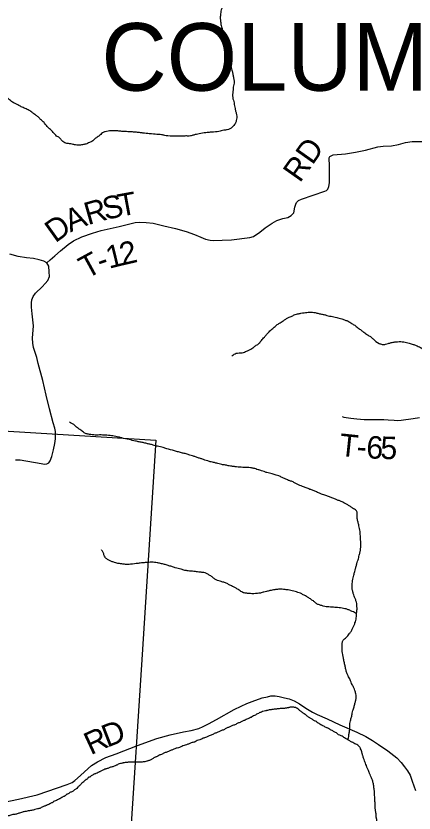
# Model space of a CAD drawing. Extents: x -13.7 to 34, y 0 to 32.3.
# Drawn here: x 27.443 to 28.447, y 15.995 to 18.005 of the extents above; entities that cross this region are included whole.
import ezdxf

# ---------------------------------------------------------------- set-up
doc = ezdxf.new("R2010")
doc.units = 0
for name, color, linetype in [('GM_X_Corporation', 7, 'Continuous'), ('GM_X_County_Road', 7, 'Continuous'), ('GM_X_County_Road_Text', 7, 'Continuous'), ('GM_X_Minor_River', 7, 'Continuous'), ('GM_X_Township_Road', 7, 'Continuous'), ('GM_X_Township_Road_Text', 7, 'Continuous'), ('GM_X_Township_Text', 7, 'Continuous')]:
    doc.layers.add(name, color=color, linetype=linetype)

msp = doc.modelspace()

# ---------------------------------------------------------------- linework, layer by layer
at = {"layer": 'GM_X_Corporation'}
msp.add_lwpolyline([(27.2726, 16.9674), (27.7957, 16.9352), (27.7886, 16.8172), (27.7611, 16.3953), (27.73, 15.9158), (26.7165, 15.9781), (26.789, 16.9963)], close=True, dxfattribs=at)
at = {"layer": 'GM_X_County_Road'}
msp.add_lwpolyline([(27.4097, 16.0217), (27.4494, 16.0299), (27.4968, 16.0413), (27.5727, 16.0673), (27.5846, 16.0726), (27.5918, 16.0776), (27.6056, 16.0899), (27.6252, 16.1077), (27.6338, 16.1151), (27.6488, 16.1247), (27.6695, 16.1352), (27.6957, 16.145), (27.7496, 16.1658), (27.7986, 16.183), (27.8324, 16.1921), (27.8654, 16.1998), (27.8845, 16.2033), (27.9043, 16.2082), (27.9153, 16.2132), (27.9286, 16.2204), (27.9491, 16.2314), (27.9931, 16.2563), (28.0108, 16.265), (28.0253, 16.2715), (28.0386, 16.2764), (28.0642, 16.2855), (28.0769, 16.2886), (28.0855, 16.2906), (28.0967, 16.2907), (28.107, 16.2888), (28.1205, 16.2858), (28.1321, 16.2832), (28.1441, 16.2785), (28.1579, 16.2704), (28.1737, 16.2601), (28.1903, 16.2498), (28.2024, 16.2442), (28.2278, 16.2326), (28.2594, 16.2181), (28.3023, 16.1992), (28.3248, 16.1884), (28.3418, 16.1782), (28.3567, 16.1684), (28.3803, 16.152), (28.4029, 16.1349), (28.4141, 16.1226), (28.423, 16.1121), (28.4303, 16.102), (28.4368, 16.0906), (28.4421, 16.0757), (28.4505, 16.0525)], dxfattribs=at)
at = {"layer": 'GM_X_Minor_River'}
for points in [[(27.9701, 18.0943), (27.9736, 18.0854), (27.9749, 18.0789), (27.9773, 18.0708), (27.9774, 18.0636), (27.9776, 18.0571), (27.9758, 18.0485), (27.9721, 18.0418), (27.9677, 18.0347), (27.9644, 18.0276), (27.9604, 18.0212), (27.9594, 18.0141), (27.9588, 18.0076), (27.9582, 17.9989), (27.9591, 17.9913), (27.9606, 17.9813), (27.9627, 17.9741), (27.9635, 17.966), (27.964, 17.958), (27.9649, 17.9512), (27.9666, 17.9443), (27.969, 17.9374), (27.9714, 17.9289), (27.9726, 17.9186), (27.9739, 17.911), (27.9744, 17.9037), (27.9772, 17.8964), (27.9822, 17.8887), (27.9843, 17.8821), (27.9876, 17.8684), (27.9897, 17.8603), (27.9912, 17.8508), (27.9932, 17.8423), (27.993, 17.8359), (27.9913, 17.8295), (27.9907, 17.8227), (27.9901, 17.8151), (27.9896, 17.7999), (27.9912, 17.7934), (27.9929, 17.7861), (27.9945, 17.7785), (27.9958, 17.7719), (27.9975, 17.7635), (27.9995, 17.7559), (28, 17.7486), (27.9986, 17.7415), (27.9957, 17.7336), (27.9894, 17.7258), (27.9824, 17.7203), (27.9758, 17.7183), (27.9674, 17.717), (27.9544, 17.7137), (27.9373, 17.7123), (27.9285, 17.7115), (27.9221, 17.7109), (27.9049, 17.7081), (27.8984, 17.7068), (27.8915, 17.7051), (27.8831, 17.7027), (27.8759, 17.7026), (27.8664, 17.7025), (27.8588, 17.702), (27.8504, 17.7019), (27.8261, 17.7027), (27.8182, 17.7041), (27.8103, 17.7059), (27.8027, 17.7065), (27.7853, 17.7079), (27.7789, 17.7085), (27.7717, 17.7091), (27.7634, 17.7101), (27.7547, 17.7112), (27.7445, 17.7123), (27.7346, 17.713), (27.7282, 17.7132), (27.7217, 17.7138), (27.7123, 17.7141), (27.7028, 17.7152), (27.6922, 17.7159), (27.6823, 17.7155), (27.6755, 17.7149), (27.6682, 17.7133), (27.6616, 17.7105), (27.6523, 17.7024), (27.6441, 17.697), (27.6367, 17.6904), (27.6286, 17.6861), (27.6193, 17.6822), (27.6113, 17.6806), (27.6006, 17.6794), (27.5931, 17.68), (27.5852, 17.6818), (27.578, 17.6832), (27.5693, 17.6843), (27.5593, 17.6911), (27.5527, 17.6981), (27.5456, 17.7025)], [(27.5456, 17.7025), (27.5375, 17.7115), (27.5276, 17.721), (27.5199, 17.7288), (27.5141, 17.7366), (27.5056, 17.7441), (27.499, 17.7508), (27.4923, 17.756), (27.4853, 17.7611), (27.4768, 17.7671), (27.4667, 17.772), (27.4566, 17.7765), (27.4484, 17.781), (27.4416, 17.7842), (27.432, 17.7899), (27.4227, 17.7978), (27.415, 17.8041), (27.4083, 17.8097), (27.4017, 17.8148), (27.3954, 17.82), (27.3891, 17.8247), (27.3817, 17.8299), (27.3724, 17.8356), (27.3656, 17.8388), (27.3585, 17.8425), (27.3495, 17.8458), (27.3417, 17.8499), (27.3353, 17.8524), (27.3278, 17.8549), (27.3203, 17.8563), (27.3127, 17.8558), (27.3054, 17.8545), (27.2989, 17.8536), (27.2898, 17.852), (27.2817, 17.8496), (27.2748, 17.8483), (27.2672, 17.8466), (27.2572, 17.8439), (27.2507, 17.8426), (27.2431, 17.8406), (27.2366, 17.8393), (27.227, 17.8373), (27.2182, 17.8357), (27.2102, 17.8341), (27.2029, 17.8317), (27.1945, 17.8285), (27.1863, 17.8242), (27.1798, 17.8199)], [(27.9877, 17.1483), (27.9955, 17.1534), (28.002, 17.1554), (28.01, 17.1555), (28.0172, 17.1568), (28.0265, 17.1611), (28.0334, 17.1639), (28.042, 17.1697), (28.049, 17.1748), (28.0563, 17.1798), (28.0619, 17.1869), (28.0694, 17.1954), (28.0749, 17.202), (28.0812, 17.209), (28.091, 17.2175), (28.098, 17.2237), (28.1062, 17.2299), (28.117, 17.2363), (28.1237, 17.2411), (28.1302, 17.245), (28.1387, 17.2482), (28.1468, 17.2525), (28.1533, 17.2541), (28.1617, 17.2558), (28.1694, 17.257), (28.1762, 17.2579), (28.1835, 17.2585), (28.1907, 17.2582), (28.1975, 17.2572), (28.2065, 17.255), (28.2152, 17.2532), (28.2235, 17.2514), (28.2302, 17.2493), (28.2374, 17.2479), (28.2446, 17.2469), (28.2517, 17.2448), (28.2581, 17.2431), (28.2649, 17.2413), (28.2731, 17.2384), (28.2806, 17.2355), (28.2892, 17.2299), (28.297, 17.2254), (28.3051, 17.2191), (28.3137, 17.2127), (28.3203, 17.2076), (28.3292, 17.2012), (28.3367, 17.1968), (28.3437, 17.1908), (28.3585, 17.1797), (28.3664, 17.1772), (28.3748, 17.1776), (28.3813, 17.1793), (28.3893, 17.1817), (28.3985, 17.1833), (28.405, 17.1839), (28.4133, 17.184), (28.4205, 17.1837), (28.428, 17.182), (28.4344, 17.1802), (28.4442, 17.1772), (28.4521, 17.1743), (28.4626, 17.1694), (28.4723, 17.1649), (28.4798, 17.1631), (28.4897, 17.1624), (28.4961, 17.1622), (28.5026, 17.1624), (28.509, 17.1622), (28.5177, 17.1615), (28.5264, 17.1601), (28.5328, 17.1587), (28.5404, 17.1577), (28.5468, 17.1571), (28.5559, 17.1564), (28.5631, 17.1551), (28.5709, 17.1521), (28.578, 17.1493), (28.5863, 17.1459), (28.5942, 17.1438), (28.6021, 17.1424), (28.6086, 17.1425), (28.6174, 17.1468), (28.6244, 17.15), (28.6318, 17.157), (28.6408, 17.165), (28.6475, 17.172), (28.6542, 17.1798), (28.6645, 17.1908), (28.6719, 17.1967), (28.6789, 17.2018), (28.6859, 17.2084), (28.6929, 17.2116), (28.7006, 17.2155), (28.7079, 17.2187), (28.7175, 17.2229), (28.7252, 17.2261), (28.7326, 17.2304)], [(28.1217, 16.8384), (28.1142, 16.8416), (28.1056, 16.8453), (28.0989, 16.8471), (28.0887, 16.8505), (28.0759, 16.8539), (28.0688, 16.8564), (28.0624, 16.8586), (28.0534, 16.8611), (28.0429, 16.8645), (28.0346, 16.8659), (28.0266, 16.867), (28.0194, 16.8668), (28.0107, 16.8671), (28.0031, 16.8677), (27.9959, 16.8687), (27.9872, 16.8698), (27.9804, 16.8708), (27.9714, 16.8726), (27.9619, 16.8741), (27.9492, 16.8775), (27.9416, 16.8793), (27.9352, 16.8806), (27.9266, 16.8832), (27.9194, 16.8853), (27.9119, 16.8883), (27.9044, 16.8904), (27.8962, 16.8933), (27.8886, 16.8959), (27.8815, 16.898), (27.8725, 16.901), (27.8627, 16.9032), (27.8529, 16.9058), (27.8428, 16.9088), (27.8232, 16.914), (27.8142, 16.9169), (27.8002, 16.9201), (27.7893, 16.9231), (27.781, 16.9253), (27.7728, 16.9271), (27.7637, 16.9293), (27.7539, 16.9311), (27.7449, 16.9333), (27.7283, 16.9369), (27.7102, 16.9413), (27.7019, 16.9435), (27.6876, 16.9462), (27.6808, 16.9472), (27.6725, 16.9482), (27.6645, 16.9485), (27.6581, 16.9487), (27.6505, 16.9486), (27.6433, 16.9485), (27.6353, 16.9491), (27.6285, 16.9501), (27.6206, 16.9519), (27.6135, 16.9555), (27.6046, 16.9623), (27.5983, 16.9667), (27.5906, 16.9738), (27.5843, 16.9778), (27.5779, 16.9806)], [(28.2792, 16.1805), (28.2816, 16.1852), (28.2825, 16.1916), (28.2836, 16.1999), (28.2846, 16.2071), (28.2844, 16.2136), (28.285, 16.2208), (28.2864, 16.228), (28.289, 16.2374), (28.2908, 16.2468), (28.2926, 16.2536), (28.2955, 16.263), (28.2977, 16.2717), (28.2999, 16.2796), (28.3005, 16.2883), (28.3, 16.2963), (28.2973, 16.3044), (28.2952, 16.3109), (28.2906, 16.3194), (28.2856, 16.3314), (28.2806, 16.341), (28.2775, 16.3487), (28.2747, 16.3576), (28.2728, 16.3667), (28.2704, 16.3763), (28.2685, 16.3863), (28.2669, 16.3951), (28.2656, 16.4023), (28.2651, 16.4099), (28.2653, 16.4175), (28.2656, 16.4244), (28.2684, 16.4315), (28.2755, 16.4377), (28.283, 16.447), (28.2878, 16.4533), (28.2914, 16.4604), (28.2951, 16.4671), (28.2976, 16.4746), (28.2997, 16.481), (28.301, 16.4874), (28.3017, 16.495), (28.3023, 16.5022), (28.303, 16.5116), (28.3025, 16.52), (28.3016, 16.5269), (28.2988, 16.5346), (28.296, 16.5419), (28.2936, 16.5488), (28.2916, 16.5569), (28.2907, 16.5652), (28.291, 16.5744), (28.2916, 16.5812), (28.293, 16.5884), (28.2948, 16.5955), (28.2973, 16.6042), (28.2991, 16.6117), (28.3012, 16.6196), (28.3034, 16.6271), (28.3055, 16.6335), (28.3086, 16.6456), (28.3107, 16.6543), (28.3121, 16.6618), (28.3128, 16.6694), (28.3126, 16.6759), (28.3121, 16.6839), (28.3116, 16.6911), (28.3111, 16.6979), (28.3105, 16.7052), (28.3089, 16.7125), (28.3076, 16.7197), (28.3056, 16.7289), (28.3036, 16.7377), (28.3031, 16.7446), (28.3037, 16.751), (28.3013, 16.7575), (28.2916, 16.7643), (28.2849, 16.7691), (28.2782, 16.7731), (28.2715, 16.7768), (28.2633, 16.7808), (28.2558, 16.7838), (28.2487, 16.7867), (28.2397, 16.79), (28.2311, 16.7933), (28.2221, 16.7967), (28.2104, 16.8008), (28.2007, 16.805), (28.1928, 16.8083), (28.1842, 16.8116), (28.1749, 16.8153), (28.1659, 16.819), (28.1591, 16.8215), (28.1524, 16.8244), (28.1457, 16.8281), (28.1374, 16.8318), (28.1299, 16.8343), (28.1217, 16.8384)], [(28.302, 16.4983), (28.291, 16.5037), (28.2827, 16.5074), (28.2752, 16.5099), (28.2688, 16.5113), (28.2616, 16.5126), (28.2541, 16.5133), (28.2473, 16.5139), (28.2393, 16.5145), (28.2321, 16.5151), (28.2253, 16.5157), (28.2178, 16.5171), (28.2099, 16.5197), (28.2027, 16.5222), (28.1961, 16.5277), (28.1894, 16.5325), (28.1816, 16.5377), (28.1753, 16.5417), (28.1675, 16.5458), (28.1604, 16.5494), (28.1536, 16.5516), (28.1469, 16.5541), (28.1397, 16.5554), (28.1329, 16.5572), (28.1265, 16.5582), (28.1178, 16.5592), (28.1049, 16.5596), (28.0954, 16.5584), (28.0835, 16.5562), (28.0751, 16.5542), (28.0682, 16.5525), (28.0594, 16.5501), (28.0518, 16.5489), (28.043, 16.5484), (28.032, 16.5487), (28.0226, 16.5498), (28.015, 16.5516), (28.0058, 16.5576), (27.9983, 16.562), (27.9912, 16.5657), (27.9826, 16.5701), (27.9755, 16.5738), (27.9669, 16.5771), (27.9579, 16.5797), (27.9511, 16.5815), (27.9444, 16.5851), (27.9381, 16.5906), (27.9303, 16.5954), (27.9232, 16.5995), (27.9165, 16.6016), (27.9078, 16.6026), (27.9006, 16.6036), (27.8915, 16.6047), (27.8772, 16.6059), (27.8692, 16.6073), (27.8594, 16.6099), (27.8523, 16.6121), (27.8448, 16.6135), (27.8358, 16.6168), (27.8267, 16.6194), (27.8173, 16.6224), (27.8075, 16.6246), (27.7989, 16.6264), (27.7921, 16.6274), (27.7856, 16.6276), (27.7773, 16.6275), (27.7708, 16.6269), (27.762, 16.6261), (27.7514, 16.6249), (27.7323, 16.6225), (27.7243, 16.6224), (27.7145, 16.6227), (27.7065, 16.6241), (27.6979, 16.6252), (27.6915, 16.6273), (27.6843, 16.6298), (27.6776, 16.6327), (27.6709, 16.6375), (27.6659, 16.6449), (27.6631, 16.6522), (27.6587, 16.6588)], [(28.1641, 16.2495), (28.1619, 16.2515), (28.1593, 16.2531), (28.1567, 16.2554), (28.1545, 16.2578), (28.1519, 16.2594), (28.1497, 16.2606), (28.1474, 16.2615), (28.144, 16.2619), (28.1364, 16.2622), (28.1326, 16.2616), (28.1299, 16.2609), (28.1269, 16.2602), (28.1238, 16.26), (28.12, 16.2593), (28.1139, 16.2588), (28.1113, 16.2585), (28.109, 16.2586), (28.1044, 16.2579), (28.1014, 16.2577), (28.0987, 16.2574), (28.0941, 16.2571), (28.0895, 16.2562), (28.0865, 16.2559), (28.0842, 16.2556), (28.0796, 16.255), (28.075, 16.2536), (28.0724, 16.2533), (28.0658, 16.2512), (28.0628, 16.2506), (28.0605, 16.2491), (28.0582, 16.2485), (28.0551, 16.2467), (28.0497, 16.2446), (28.0473, 16.2424), (28.0416, 16.2403), (28.0373, 16.2374), (28.0346, 16.2359), (28.0296, 16.2334), (28.0254, 16.2324), (28.0211, 16.2295), (28.0173, 16.2285), (28.0142, 16.2271), (28.008, 16.2239), (28.0042, 16.2225), (28.0007, 16.2211), (27.9934, 16.2172), (27.9891, 16.2162), (27.9861, 16.2147), (27.9791, 16.2112), (27.9757, 16.2102), (27.9726, 16.2087), (27.9652, 16.2044), (27.961, 16.2034), (27.9579, 16.202), (27.9506, 16.1981), (27.9468, 16.1971), (27.9433, 16.1956), (27.9352, 16.1914), (27.9306, 16.19), (27.9232, 16.1864), (27.9186, 16.1851), (27.9148, 16.1837), (27.9067, 16.1801), (27.9002, 16.1785), (27.8952, 16.1752), (27.8871, 16.1728), (27.8798, 16.1696), (27.8763, 16.1686), (27.8733, 16.1676), (27.8671, 16.1659), (27.8614, 16.1634), (27.8556, 16.1606), (27.8495, 16.1592), (27.8456, 16.1582), (27.8375, 16.1547), (27.8341, 16.1537), (27.831, 16.1523), (27.8237, 16.1487), (27.8198, 16.1477), (27.8164, 16.1463), (27.8098, 16.1427), (27.806, 16.1417), (27.8033, 16.1403), (27.7975, 16.137), (27.7948, 16.1364), (27.7874, 16.1317), (27.7847, 16.1306), (27.7782, 16.1274), (27.7755, 16.1267), (27.7732, 16.1261), (27.7682, 16.1247), (27.7636, 16.1241), (27.7598, 16.1238), (27.7564, 16.1239), (27.7526, 16.1237), (27.7473, 16.1239)], [(28.3923, 15.9068), (28.3901, 15.9092), (28.3887, 15.9122), (28.3885, 15.9179), (28.3886, 15.9202), (28.3891, 15.924), (28.3888, 15.9271), (28.3885, 15.9305), (28.3882, 15.9328), (28.3869, 15.9374), (28.3836, 15.942), (28.3806, 15.9444), (28.3776, 15.9457), (28.3735, 15.9481), (28.3706, 15.9493), (28.3687, 15.952), (28.3658, 15.9548), (28.3626, 15.9598), (28.3593, 15.9637), (28.3567, 15.968), (28.3539, 15.973), (28.3532, 15.9757), (28.3523, 15.9815), (28.3516, 15.9841), (28.3513, 15.9868), (28.3508, 15.994), (28.3505, 15.9967), (28.3498, 15.9998), (28.349, 16.0078), (28.3483, 16.012), (28.3486, 16.0188), (28.3483, 16.0215), (28.3481, 16.028), (28.3478, 16.0302), (28.3475, 16.0329), (28.3474, 16.0398), (28.3471, 16.0443), (28.3466, 16.0516), (28.3463, 16.0539), (28.3457, 16.0588), (28.3454, 16.0622), (28.3448, 16.0661), (28.3435, 16.0714), (28.3425, 16.0753), (28.3404, 16.0814), (28.3383, 16.086), (28.3358, 16.0926), (28.3344, 16.0949), (28.3337, 16.0972), (28.332, 16.1022), (28.3284, 16.1095), (28.3277, 16.1122), (28.3267, 16.1149), (28.3242, 16.1207), (28.3224, 16.1246), (28.3207, 16.1299), (28.319, 16.1338), (28.318, 16.1384), (28.3169, 16.1411), (28.3159, 16.1453), (28.3152, 16.1476), (28.3142, 16.1518), (28.3121, 16.1572), (28.3107, 16.1599), (28.3089, 16.1622), (28.3067, 16.165), (28.3022, 16.1678), (28.2974, 16.1699), (28.2925, 16.1731), (28.2895, 16.1743), (28.2866, 16.1759), (28.2795, 16.1803), (28.2754, 16.1824), (28.268, 16.1875), (28.2631, 16.1904), (28.2564, 16.1925), (28.2512, 16.1972), (28.2467, 16.1993), (28.24, 16.2033), (28.2363, 16.2049), (28.2337, 16.2065), (28.2281, 16.2098), (28.2251, 16.211), (28.2169, 16.2155), (28.2143, 16.2167), (28.212, 16.2179), (28.2072, 16.2211), (28.205, 16.2223), (28.1987, 16.2267), (28.196, 16.2275), (28.1901, 16.2319), (28.1864, 16.2339), (28.1838, 16.2352), (28.1804, 16.2372), (28.1774, 16.2396), (28.17, 16.2455), (28.1641, 16.2495)], [(27.7473, 16.1239), (27.7443, 16.1236), (27.7344, 16.1239), (27.7298, 16.1237), (27.7264, 16.1234), (27.7218, 16.1228), (27.7184, 16.1226), (27.7138, 16.1216), (27.7112, 16.1209), (27.7066, 16.1199), (27.7012, 16.1182), (27.6973, 16.116), (27.695, 16.1153), (27.6873, 16.1122), (27.6835, 16.1112), (27.68, 16.1101), (27.6731, 16.1073), (27.6701, 16.1067), (27.6674, 16.1056), (27.6627, 16.1035), (27.6593, 16.1021), (27.6558, 16.0999), (27.6531, 16.0993), (27.6508, 16.0978), (27.645, 16.0946), (27.6419, 16.0939), (27.6396, 16.0929), (27.6361, 16.0907), (27.6327, 16.0889), (27.6291, 16.086), (27.6257, 16.0846), (27.6225, 16.0809), (27.6198, 16.0795), (27.614, 16.0743), (27.6093, 16.0707), (27.6069, 16.0674), (27.6006, 16.0615), (27.5967, 16.0574), (27.594, 16.0556), (27.5909, 16.0534), (27.5842, 16.0487), (27.5808, 16.0477), (27.5746, 16.0437), (27.5719, 16.0427), (27.5696, 16.0412), (27.5645, 16.0372), (27.5614, 16.0362), (27.5591, 16.0347), (27.5537, 16.0315), (27.551, 16.0304), (27.5483, 16.029), (27.5429, 16.0258), (27.5383, 16.0244), (27.5355, 16.0218), (27.5328, 16.0208), (27.5305, 16.0197), (27.5263, 16.0172), (27.5236, 16.0162), (27.5213, 16.0151), (27.5189, 16.014), (27.5163, 16.013), (27.5128, 16.0116), (27.5093, 16.0105), (27.5051, 16.0077), (27.5012, 16.0066), (27.4978, 16.0056), (27.4913, 16.0043), (27.4867, 16.0026), (27.4829, 16.0019), (27.4802, 16.0013), (27.4745, 16.0007), (27.4687, 15.9994), (27.463, 15.9984), (27.4596, 15.9978), (27.4549, 15.9956), (27.4504, 15.9946), (27.4431, 15.9922), (27.4385, 15.9916), (27.4328, 15.9907), (27.4236, 15.9879), (27.4186, 15.9873), (27.4151, 15.9856), (27.4125, 15.9849), (27.4094, 15.9842), (27.4071, 15.9832), (27.404, 15.9814), (27.4001, 15.9792), (27.3959, 15.9782), (27.3924, 15.9757), (27.3893, 15.9746), (27.3867, 15.974), (27.3813, 15.9719), (27.3767, 15.9712), (27.3732, 15.9695), (27.3698, 15.9688), (27.3671, 15.9681), (27.3602, 15.9665)]]:
    msp.add_spline(points, degree=3, dxfattribs=at)
at = {"layer": 'GM_X_Township_Road'}
for points in [[(27.521, 17.3827), (27.5299, 17.3903), (27.541, 17.4004), (27.5553, 17.4131), (27.575, 17.4293), (27.5882, 17.4381), (27.6093, 17.448), (27.6364, 17.4578), (27.6578, 17.4646), (27.7034, 17.4745), (27.7233, 17.4792), (27.7439, 17.4845), (27.7539, 17.4856), (27.7719, 17.4849), (27.789, 17.4825), (27.8164, 17.4757), (27.8456, 17.4694), (27.8723, 17.4617), (27.8931, 17.4543), (27.909, 17.4474), (27.9211, 17.4425), (27.9325, 17.44), (27.9415, 17.4392), (27.9627, 17.4396), (27.9862, 17.4406), (28.0326, 17.4463), (28.042, 17.4494), (28.0581, 17.4602), (28.0718, 17.4708), (28.0891, 17.4827), (28.1008, 17.4892), (28.1157, 17.4943), (28.1287, 17.4972), (28.1373, 17.5019), (28.1434, 17.509), (28.1463, 17.5231), (28.1483, 17.5307), (28.1508, 17.5348), (28.1557, 17.5398), (28.163, 17.5437), (28.2216, 17.5633), (28.2257, 17.5654), (28.2294, 17.5682), (28.2318, 17.5752), (28.2335, 17.5848), (28.2335, 17.6266), (28.2328, 17.6472), (28.2341, 17.6507), (28.2377, 17.6526), (28.2431, 17.6554), (28.2741, 17.6579), (28.2994, 17.6619), (28.3243, 17.6666), (28.3551, 17.675), (28.3686, 17.6771), (28.3896, 17.6777), (28.4072, 17.6815), (28.425, 17.6864), (28.4415, 17.6885), (28.4664, 17.6887)], [(27.4422, 16.8856), (27.4477, 16.8862), (27.4539, 16.8858), (27.5067, 16.8764), (27.5153, 16.8749), (27.5208, 16.8757), (27.5262, 16.8788), (27.5299, 16.8838), (27.5338, 16.894), (27.5377, 16.9109), (27.5415, 16.9276), (27.543, 16.9392), (27.5434, 16.9493), (27.5432, 16.9573), (27.5412, 16.9655), (27.5375, 16.979), (27.528, 17.0147), (27.5192, 17.049), (27.5108, 17.086), (27.4995, 17.1287), (27.496, 17.1439), (27.4875, 17.1692), (27.4855, 17.1802), (27.4853, 17.193), (27.4872, 17.224), (27.4839, 17.2542), (27.4824, 17.271), (27.4822, 17.2818), (27.4837, 17.2891), (27.4867, 17.2979), (27.4925, 17.3063), (27.5093, 17.3221), (27.5173, 17.3308), (27.5239, 17.3383), (27.5278, 17.3482), (27.5274, 17.3599), (27.526, 17.3743), (27.521, 17.3827), (27.5134, 17.387), (27.5021, 17.3903), (27.4874, 17.394), (27.4703, 17.3958), (27.449, 17.3987), (27.4278, 17.4047)], [(28.2654, 16.9954), (28.2699, 16.9939), (28.2871, 16.9914), (28.3023, 16.9898), (28.321, 16.9879), (28.3383, 16.9879), (28.3572, 16.9879), (28.3703, 16.9876), (28.3817, 16.9867), (28.3966, 16.986), (28.4058, 16.9856), (28.4144, 16.9863), (28.4445, 16.9904), (28.4603, 16.9926)]]:
    msp.add_lwpolyline(points, dxfattribs=at)

# ---------------------------------------------------------------- texts
at = {"layer": 'GM_X_County_Road_Text'}
for s, rotation, p in [('D', 21.1845, (27.6732, 16.16)), ('R', 24.8839, (27.6318, 16.1407))]:
    msp.add_text(s, height=0.0568, rotation=rotation, dxfattribs=at).set_placement(p)
at = {"layer": 'GM_X_Township_Road_Text'}
for s, height, rotation, p in [('RD', 0.05682, 54.8048, (28.1589, 17.5827)), ('S', 0.0568, 13.1627, (27.6688, 17.4903)), ('T', 0.0568, 10.4022, (27.7055, 17.4989)), ('R', 0.0568, 15.9298, (27.6247, 17.4777)), ('A', 0.0568, 22.5036, (27.5801, 17.4591)), ('D', 0.0568, 35.5504, (27.5424, 17.4317)), ('1', 0.0568, 13.8141, (27.6778, 17.3677)), ('2', 0.0568, 13.1452, (27.7116, 17.376)), ('T', 0.0568, 28.6737, (27.622, 17.3412)), ('-', 0.0568, 18.7213, (27.6569, 17.3606)), ('T', 0.0568, 354.0408, (28.2563, 16.8963)), ('6', 0.0568, 357.3237, (28.3254, 16.89)), ('5', 0.0568, 358.2298, (28.3613, 16.8884)), ('-', 0.0568, 356.1262, (28.3008, 16.8917))]:
    msp.add_text(s, height=height, rotation=rotation, dxfattribs=at).set_placement(p)
at = {"layer": 'GM_X_Township_Text'}
msp.add_text('COLUMBIA', height=0.17045, rotation=0, dxfattribs=at).set_placement((27.6588, 17.8169))

doc.saveas('drawing.dxf')
